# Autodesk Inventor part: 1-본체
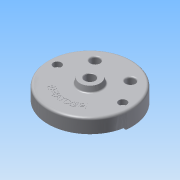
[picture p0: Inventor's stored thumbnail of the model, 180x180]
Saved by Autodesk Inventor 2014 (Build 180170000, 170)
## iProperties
Created: 2015-06
Part Number: 1-본체
Material: 알루미늄 6061
Document SubType Name: Modeling
Designer: Administrator
Density: 2.71 g/cm^3
Appearance: 알루미늄 - 평지
Mass: 1431.69 g
Surface Area: 1069.45 cm^2
Volume: 528.298 cm^3
Author: Administrator
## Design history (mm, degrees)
sketch "스케치1"
  geometry: C1 r 95 at (0, 0); 1 further point
  constraints: 1 centre point, 1 coincident
  dimensions: "d0" = 190 diameter of C1
extrude "돌출1" new body sketch "스케치1" distance "d1" = 32; taper "d2" = 0 deg
feature "쉘1" dims "d3" = 19, "d4" = 5
sketch "스케치2"
  geometry: C1 r 95 at (0, 0) reference; C2 r 26 at (0, 0)
  constraints: 1 centre point, 1 coincident
  dimensions: "d5" = 52 diameter of C2
extrude "돌출2" join sketch "스케치2" distance "d6" = 12; taper "d7" = -15 deg
sketch "스케치3"
  geometry: C1 r 90 at (0, 0) reference; C2 r 35 at (0, 0)
  constraints: 1 centre point, 1 coincident
  dimensions: "d8" = 70 diameter of C2
extrude "돌출3" join sketch "스케치3" distance "d9" = 10; taper "d10" = 0 deg
hole "구멍1" diameter "d13" = 23; stored, may be unused: countersink angle "d17" = 90 deg, drill point angle "d19" = 0 deg; dims "d11" = 10, "d12" = 10, "d14" = 6, "d15" = 50, "d16" = 15, "d18" = 8
sketch "스케치4"
  geometry: L1 (-45.033, 16)-(-75.657, 16); L2 (45.033, 16)-(75.657, 16); C1 r 95 at (0, 0) reference; A1 r 90 centre (0, 0) between (-88.566, 16) and (88.566, 16) reference; A2 r 42 centre (0, 0) between (36.373, 21) and (-36.373, 21); A3 r 90 centre (0, 0) between (85.114, 29.25) and (-85.114, 29.25); A4 r 10 centre (-75.657, 26) between (-85.114, 29.25) and (-75.657, 16); A5 r 10 centre (75.657, 26) between (75.657, 16) and (85.114, 29.25); A6 r 10 centre (-45.033, 26) between (-45.033, 16) and (-36.373, 21); A7 r 10 centre (45.033, 26) between (36.373, 21) and (45.033, 16); 2 further points
  constraints: 18 point on circle, 8 tangent, 6 centre point, 4 end point, 4 point on line, 3 equal radius, 2 coincident, 2 collinear, 1 horizontal
  dimensions: "d20" = 84 diameter of A2; "d21" = 16 distance from line of A1.centre L1; "d22" = 10 radius of A4; "d23" = 10 radius of A6
extrude "돌출4" cut sketch "스케치4" distance "d24" = 20; taper "d25" = 0 deg
sketch "스케치5"
  geometry: L1 (-45.033, 16)-(-75.657, 16) reference; L2 (-59, -19)-(59, -19); L3 (-59, -19)-(-59, -14); L4 (-41, -19)-(-41, -14); L5 (0, -19)-(0, 0); L6 (59, -19)-(59, -14); L7 (41, -19)-(41, -14); C1 r 35 at (0, 0) reference; A1 r 90 centre (0, 0) between (-85.114, 29.25) and (85.114, 29.25) reference; A2 r 41 centre (0, -19) between (-41, -19) and (41, -19); A3 r 59 centre (0, -19) between (-59, -19) and (59, -19); A4 r 9 centre (-50, -14) between (-41, -14) and (-59, -14); A5 r 9 centre (50, -14) between (59, -14) and (41, -14)
  constraints: 12 end point, 8 point on circle, 4 centre point, 4 parallel, 4 tangent, 3 symmetric about line, 2 point on line, 1 coincident, 1 perpendicular, 1 vertical alignment, 1 other
  dimensions: "d27" = 19 distance of A2.centre A1.centre; "d29" = 5 distance of L2.start L3.end; "d30" = 41 radius of A2; "d31" = 59 radius of A3
extrude "돌출5" cut sketch "스케치5" distance "d32" = 7; taper "d33" = 0 deg
sketch "스케치6"
  geometry: C1 r 90 at (0, 0) reference; C2 r 9 at (-74, 0); C3 r 9 at (74, 0)
  constraints: 2 centre point, 2 horizontal alignment, 1 equal radius
  dimensions: "d34" = 18 diameter of C2; "d35" = 148 distance of C3.centre C2.centre; "d36" = 74 distance of C3.centre C1.centre
extrude "돌출6" join sketch "스케치6" stored distance "d37" = 7; taper "d38" = 0 deg
sketch "스케치7"
  geometry: C1 r 9 at (-74, 0) reference; C2 r 9 at (74, 0) reference; 2 further points
  constraints: 2 coincident
hole "구멍2" sketch "스케치7" at (-74, 0), (74, 0) diameter "d39" = 11; stored, may be unused: countersink angle "d43" = 90 deg, drill point angle "d45" = 0 deg; dims "d40" = 6, "d41" = 18, "d42" = 11, "d44" = 8
sketch "스케치8"
  geometry: C1 r 90 at (0, 0); C2 r 15 at (-40, 52); C3 r 15 at (40, 52); C4 r 9 at (-74, 0)
  constraints: 4 centre point, 1 equal radius, 1 horizontal alignment
  dimensions: "d46" = 52 vertical distance of C4.centre C2.centre; "d47" = 30 diameter of C2; "d48" = 80 distance of C3.centre C2.centre; "d49" = 40 horizontal distance of C1.centre C2.centre
extrude "돌출7" join sketch "스케치8" stored distance "d50" = 7; taper "d51" = 0 deg
sketch "스케치15"
  geometry: C1 r 15 at (0, 0) reference; C2 r 15 at (80, 0) reference; C3 r 15 at (0, 0); C4 r 15 at (80, 0); 1 further point
  constraints: 2 centre point, 2 coincident, 2 concentric
  node "투영된 루프3"
sketch "스케치9"
  geometry: C1 r 15 at (0, 0) reference; C2 r 15 at (80, 0) reference; 3 further points
  constraints: 2 coincident
hole "구멍3" sketch "스케치9" at (0, 0), (80, 0) diameter "d52" = 20; stored, may be unused: countersink angle "d56" = 90 deg, drill point angle "d58" = 0 deg; dims "d53" = 6, "d54" = 18, "d55" = 11, "d57" = 8
sketch "스케치11"
  geometry: L1 (-95, 0)-(95, 0); L2 (-94.075, -13.221)-(-89.124, -12.526); L3 (89.124, -12.526)-(94.075, -13.221); A1 r 90 centre (0, 0) between (-89.124, -12.526) and (89.124, -12.526) reference; A2 r 95 centre (0, 0) between (-95, 0) and (95, 0) reference
  constraints: 6 end point, 6 point on circle, 1 horizontal
  dimensions: "d63" = 8 deg angle of L2 L1; "d64" = 8 deg angle of L3 L1; "d65" = 0 distance from line of A2.centre L3; "d66" = 0 distance from line of A2.centre L1; "d67" = 0 distance from line of A2.centre L2
extrude "돌출9" join sketch "스케치11" distance "d68" = 5; taper "d69" = 0 deg
sketch "스케치12"
  geometry: C1 r 9 at (-74, 0) reference; C2 r 5.5 at (74, 0) reference; C3 r 9 at (74, 0) reference; C4 r 9 at (-74, 0); C5 r 9 at (74, 0); C6 r 5.5 at (74, 0); C7 r 5.5 at (-74, 0) reference; C8 r 5.5 at (-74, 0)
  constraints: 4 centre point, 4 coincident, 4 concentric
extrude "돌출10" join sketch "스케치12" distance "d70" = 5; taper "d71" = 0 deg
fillet "모깎기1" dims "d72" = 3, "d73" = 5, "d74" = 1
chamfer "모따기1" distance "d75" = 1; stored, may be unused: second distance "d76" = 2, angle "d77" = 45 deg
sketch "스케치13"
  geometry: C1 r 90 at (0, 0) reference; C2 r 68 at (0, 0)
  constraints: 1 centre point, 1 coincident, 1 other
  dimensions: "d78" = 136 diameter of C2
feature "엠보싱1" sketch "스케치13" dims "d79" = 0.5, "d80" = 0
extrude "돌출11" join sketch "스케치15" distance "d82" = 5; taper "d83" = 0 deg
sketch "스케치16"
  geometry: C1 r 15 at (0, 0) reference; C2 r 15 at (80, 0) reference; 3 further points
  constraints: 2 coincident
hole "구멍4" sketch "스케치16" at (0, 0), (80, 0) diameter "d84" = 20; stored, may be unused: countersink angle "d88" = 90 deg, drill point angle "d90" = 118 deg; dims "d85" = 6, "d86" = 4, "d87" = 2, "d89" = 8
sketch "스케치17"
  geometry: L1 (-6, 13.748)-(-6, -13.748); L2 (6, 13.748)-(6, -13.748); A1 r 15 centre (0, 0) between (-6, 13.748) and (-6, -13.748) reference; 1 further point
  constraints: 4 end point, 4 point on circle, 1 parallel, 1 vertical
  dimensions: "d91" = 12 distance between parallel lines of L2 L1
extrude "돌출12" cut sketch "스케치17" distance "d92" = 3; taper "d93" = 0 deg
sketch "스케치18"
  geometry: L1 (-13.428, 6.684)-(14.032, 5.301); L2 (-14.032, -5.301)-(13.428, -6.684); A1 r 15 centre (0, 0) between (-13.428, 6.684) and (14.032, 5.301) reference; 1 further point
  constraints: 4 end point, 4 point on circle, 2 parallel
  dimensions: "d94" = 12 distance between parallel lines of L2 L1; "d96" = 59.94662 distance from line of point (-40, -52) L1
extrude "돌출13" cut sketch "스케치18" distance "d97" = 3; taper "d98" = 0 deg
sketch "스케치19"
  geometry: L1 (-45.033, 16)-(-75.657, 16) reference; L2 (75.657, 16)-(45.033, 16) reference; L3 (-45.033, 16)-(-75.657, 16) reference; L4 (75.657, 16)-(45.033, 16) reference; C1 r 18 at (-40, 52) reference; C2 r 18 at (40, 52) reference; A1 r 10 centre (-75.657, 26) between (-85.114, 29.25) and (-75.657, 16) reference; A2 r 10 centre (-45.033, 26) between (-45.033, 16) and (-36.373, 21) reference; A3 r 42 centre (0, 0) between (36.373, 21) and (-36.373, 21) reference; A4 r 10 centre (45.033, 26) between (36.373, 21) and (45.033, 16) reference; A5 r 10 centre (75.657, 26) between (75.657, 16) and (85.114, 29.25) reference; A6 r 90 centre (0, 0) between (85.114, 29.25) and (-85.114, 29.25) reference; A7 r 10 centre (-45.033, 26) between (-45.033, 16) and (-36.373, 21) reference; A8 r 42 centre (0, 0) between (36.373, 21) and (-36.373, 21) reference; A9 r 10 centre (45.033, 26) between (36.373, 21) and (45.033, 16) reference; A10 r 90 centre (0, 0) between (85.114, 29.25) and (-85.114, 29.25) reference; A11 r 10 centre (-75.657, 26) between (-85.114, 29.25) and (-75.657, 16) reference; A12 r 10 centre (75.657, 26) between (75.657, 16) and (85.114, 29.25) reference
extrude "돌출14" cut sketch "스케치19" distance "d99" = 5; taper "d100" = 0 deg
sketch "스케치20"
  geometry: C1 r 18 at (0, 0) reference; C2 r 15 at (0, 0) reference; C3 r 15 at (-80, 0) reference; C4 r 18 at (-80, 0) reference; 1 further point
extrude "돌출15" cut sketch "스케치20" distance "d101" = 5; taper "d102" = 0 deg
fillet "모깎기2" dims "d103" = 3, "d104" = 0.3
node "솔리드1"
node "투영된 루프1"
node "투영된 루프4"
node "투영된 루프5"
other parameters: "d26" = 82, "d28" = 118
